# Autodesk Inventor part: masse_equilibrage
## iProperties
Created: 2011-01
Part Number: masse_equilibrage
Document SubType Name: Modeling
Designer: eric
Density: 1 g/cm^3
Mass: 2.5982 g
Surface Area: 33.1714 cm^2
Volume: 2.5982 cm^3
Author: eric
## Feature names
1. Base1
